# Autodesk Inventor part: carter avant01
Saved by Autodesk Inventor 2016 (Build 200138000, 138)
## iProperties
Created: 2013-10
Part Number: carter avant01
Material: Générique
Document SubType Name: Modeling
Designer: Bruno
Density: 1 g/cm^3
Appearance: Par défaut
Author: Bruno
Sending System: SolidWorks 2013
Last Author: christophe
Last Saved: 2014-02-15
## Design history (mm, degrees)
feature "Enlèvement de matière-Balayage7"
node "Solide1"
